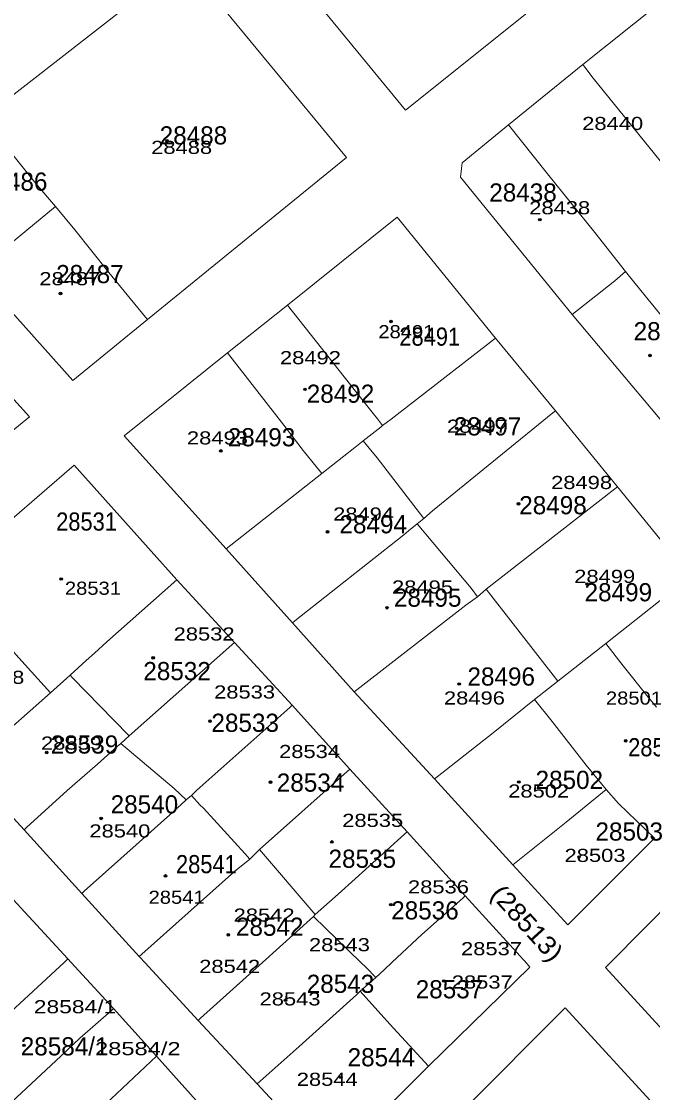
# Model space of a CAD drawing. Extents: x 650553 to 652508, y 239277 to 241647.
# Drawn here: x 651405.4 to 651530.5, y 240724.2 to 240936.5 of the extents above; entities that cross this region are included whole.
import ezdxf

# ---------------------------------------------------------------- set-up
doc = ezdxf.new("R2010")
doc.units = 0
doc.header["$PDMODE"] = 32
doc.header["$PDSIZE"] = 0.5
for name, color, linetype in [('19', 7, 'Continuous'), ('20', 7, 'Continuous'), ('6', 7, 'Continuous')]:
    doc.layers.add(name, color=color, linetype=linetype)
doc.layers.add('3', color=7, linetype='Continuous', lineweight=13)
doc.layers.add('5', color=7, linetype='Continuous', lineweight=13)

msp = doc.modelspace()

# ---------------------------------------------------------------- linework, layer by layer
at = {"layer": '3'}
for p, q in [((651446.19, 240870.77), (651458.08, 240880.24)), ((651522.14, 240750), (651543.89, 240772.06))]:
    msp.add_line(p, q, dxfattribs=at)
for points in [[(651546.27, 240951.81), (651531.67, 240939.91), (651516.66, 240927.91), (651501.92, 240915.97)], [(651437.75, 240948.31), (651469.83, 240909.51), (651430.38, 240877.39)], [(651509.19, 240941.06), (651481.51, 240918.86), (651464.1, 240940.04)], [(651501.92, 240915.97), (651492.74, 240908.47), (651492.4, 240905.62), (651514.54, 240878.38)], [(651430.38, 240877.39), (651415.54, 240865.35), (651396.3, 240886.8), (651380.56, 240904.16)], [(651458.08, 240880.24), (651479.87, 240897.65), (651499.31, 240873.72)], [(651388.92, 240878), (651406.98, 240858.1), (651385.53, 240840.68)], [(651514.54, 240878.38), (651535.4, 240853.59), (651549.69, 240835.74)], [(651499.31, 240873.72), (651511.23, 240859.29), (651523.5, 240844.24), (651538, 240826.47)], [(651445.92, 240831.96), (651425.74, 240854.38), (651446.19, 240870.77)], [(651390.1, 240826.37), (651415.79, 240848.55), (651436.19, 240825.84)], [(651502.8, 240769.36), (651487.27, 240786.38), (651471.34, 240803.62), (651459.09, 240817.33), (651445.92, 240831.96)], [(651436.19, 240825.84), (651447.59, 240813.4), (651459.05, 240800.99), (651470.46, 240788.31), (651481.81, 240775.9), (651493.35, 240763.21), (651505.639, 240749.709)], [(651375, 240810.41), (651394.45, 240788.7), (651405.88, 240776.28), (651417.31, 240763.69), (651428.702, 240751.214)], [(651375, 240793.89), (651381.88, 240786.41), (651393.61, 240773.4), (651414.55, 240750.7), (651415.19, 240750)], [(651530.84, 240774.62), (651513.67, 240757.48), (651502.8, 240769.36)], [(651432.124, 240731.442), (651423.639, 240740.872), (651415.19, 240750)], [(651428.702, 240751.214), (651428.86, 240751.04), (651429.82, 240750)], [(651429.82, 240750), (651440.379, 240738.517), (651452.07, 240725.954)], [(651486.051, 240729.467), (651506.176, 240749.102), (651505.639, 240749.709)], [(651522.14, 240750), (651521.163, 240749.011), (651539.59, 240728.862)], [(651492.971, 240720.815), (651513.155, 240740.984), (651531.466, 240721.038), (651544.042, 240707.095)], [(651450.066, 240711.621), (651441.147, 240721.392), (651432.124, 240731.442)], [(651452.07, 240725.954), (651466.7, 240710.154), (651486.051, 240729.467)]]:
    msp.add_lwpolyline(points, dxfattribs=at)
at = {"layer": '5'}
for p, q in [((651396.3, 240886.8), (651412.1, 240899.78)), ((651525.14, 240886.94), (651528.17, 240883.13)), ((651537.239, 240871.964), (651528.17, 240883.13)), ((651476.97, 240856.39), (651476.65, 240856.11)), ((651464.93, 240846.88), (651471.48, 240852.07)), ((651511.71, 240805.76), (651497.47, 240823.96)), ((651411.14, 240803.44), (651414.99, 240806.932)), ((651426.72, 240794.89), (651423.65, 240798)), ((651414.55, 240750.7), (651413.8, 240750))]:
    msp.add_line(p, q, dxfattribs=at)
for points in [[(651397.68, 240917.22), (651399.98, 240918.99), (651432.63, 240944.47)], [(651516.66, 240927.91), (651517.037, 240927.41), (651518.73, 240925.21)], [(651518.73, 240925.21), (651560.268, 240873.976), (651560.673, 240873.476)], [(651430.38, 240877.39), (651429.968, 240877.89), (651422.71, 240886.7), (651415.97, 240895.15), (651412.1, 240899.78), (651408.2, 240904.34), (651401.46, 240912.71), (651400.99, 240913.24), (651397.68, 240917.22)], [(651501.92, 240915.97), (651509.67, 240906.26), (651519, 240894.67), (651525.14, 240886.94), (651523.01, 240885.07), (651514.54, 240878.38)], [(651458.08, 240880.24), (651475.08, 240858.77), (651475.98, 240857.69), (651476.97, 240856.39), (651478.63, 240857.66), (651499.31, 240873.72)], [(651446.19, 240870.77), (651457.86, 240855.89), (651461.23, 240851.46), (651464.93, 240846.88), (651445.92, 240831.96)], [(651511.23, 240859.29), (651510.73, 240858.884), (651486.86, 240839.48)], [(651473.09, 240853.35), (651475.46, 240855.22), (651476.65, 240856.11)], [(651485.13, 240837.96), (651475.87, 240849.97), (651474.3, 240851.91), (651473.09, 240853.35), (651471.48, 240852.07)], [(651497.47, 240823.96), (651523, 240843.85), (651523.5, 240844.24)], [(651483.82, 240836.95), (651485.13, 240837.96), (651486.86, 240839.48)], [(651495.76, 240822.48), (651494.54, 240824.16), (651485.54, 240834.9), (651484.88, 240835.66), (651483.82, 240836.95), (651482.07, 240835.5), (651481.16, 240834.77)], [(651459.09, 240817.33), (651459.59, 240817.725), (651481.16, 240834.77)], [(651538, 240826.47), (651521.21, 240813.2), (651524.67, 240808.76), (651529.34, 240802.91), (651531.25, 240800.58)], [(651419.83, 240811.26), (651422.29, 240813.51), (651436.19, 240825.84)], [(651497.47, 240823.96), (651495.76, 240822.48), (651493.43, 240820.77)], [(651471.34, 240803.62), (651471.84, 240804.008), (651493.43, 240820.77)], [(651426.72, 240794.89), (651447.09, 240812.957), (651447.59, 240813.4)], [(651507.07, 240802.14), (651511.71, 240805.76), (651521.21, 240813.2)], [(651411.14, 240803.44), (651404.847, 240810.382), (651402.77, 240812.7)], [(651414.99, 240806.932), (651418.188, 240809.832), (651419.83, 240811.26)], [(651423.65, 240798), (651415.475, 240806.432), (651414.99, 240806.932)], [(651411.14, 240803.44), (651394.95, 240789.142), (651394.45, 240788.7)], [(651440.75, 240784.68), (651458.55, 240800.544), (651459.05, 240800.99)], [(651487.27, 240786.38), (651487.77, 240786.772), (651498.9, 240795.49), (651507.07, 240802.14), (651510.57, 240797.75), (651517.32, 240789.13), (651521.26, 240784.29), (651513.33, 240777.83), (651502.8, 240769.36)], [(651438.05, 240782.21), (651435.61, 240784.49), (651425.05, 240793.4), (651426.72, 240794.89)], [(651425.05, 240793.4), (651424.33, 240792.82), (651420.45, 240789.29), (651414.43, 240784.05)], [(651452.56, 240772.42), (651469.96, 240787.866), (651470.46, 240788.31)], [(651414.43, 240784.05), (651406.38, 240776.734), (651405.88, 240776.28)], [(651439.09, 240783.1), (651440.05, 240784.08), (651440.75, 240784.68)], [(651521.26, 240784.29), (651523.72, 240781.48), (651530.84, 240774.62)], [(651450.61, 240770.46), (651449.63, 240771.58), (651441.46, 240780.6), (651440.74, 240781.22), (651439.09, 240783.1), (651438.05, 240782.21), (651435.39, 240779.8)], [(651435.39, 240779.8), (651417.81, 240764.136), (651417.31, 240763.69)], [(651471.51, 240766.59), (651481.31, 240775.448), (651481.81, 240775.9)], [(651447.59, 240768.02), (651450.61, 240770.46), (651452.56, 240772.42)], [(651463.28, 240759.08), (651463.57, 240759.48), (651452.56, 240772.42)], [(651428.702, 240751.214), (651429.22, 240751.675), (651447.59, 240768.02)], [(651463.57, 240759.48), (651468.15, 240763.55), (651471.51, 240766.59)], [(651493.35, 240763.21), (651492.85, 240762.765), (651484.72, 240755.53), (651478.838, 240750.049)], [(651472.62, 240750), (651463.28, 240759.08), (651453.16, 240750)], [(651397.508, 240716.45), (651396.065, 240717.916), (651388.221, 240726.041), (651389.808, 240727.583), (651392.535, 240729.948), (651401.538, 240738.647), (651413.8, 240750)], [(651440.379, 240738.517), (651440.879, 240738.956), (651453.16, 240750)], [(651471.799, 240743.591), (651472.531, 240744.345), (651475.628, 240747.006), (651477.271, 240748.54), (651478.838, 240750.049)], [(651475.628, 240747.006), (651473.674, 240748.977), (651472.62, 240750)], [(651452.07, 240725.954), (651460.412, 240733.359), (651471.799, 240743.591)], [(651486.051, 240729.467), (651478.41, 240737.746), (651472.531, 240744.345)], [(651416.952, 240735.001), (651423.139, 240740.433), (651423.639, 240740.872)], [(651397.508, 240716.45), (651401.448, 240720.514), (651413.187, 240731.421), (651416.952, 240735.001)], [(651406.137, 240706.385), (651417.43, 240717.455), (651422.004, 240721.904), (651432.124, 240731.442)]]:
    msp.add_lwpolyline(points, dxfattribs=at)
at = {"layer": '6'}
for p in [(651434.202, 240912.85), (651508.124, 240897.175), (651413.108, 240882.565), (651478.629, 240877.02), (651529.973, 240870.265), (651461.566, 240863.56), (651491.637, 240855.84), (651444.88, 240851.365), (651503.891, 240840.885), (651466.049, 240835.34), (651413.249, 240825.995), (651517.472, 240825), (651477.817, 240820.285), (651431.484, 240810.365), (651492.145, 240805.17), (651442.742, 240797.805), (651525.15, 240793.91), (651410.368, 240791.606), (651454.735, 240785.725), (651503.958, 240785.75), (651421.177, 240778.545), (651466.907, 240773.895), (651515.897, 240770.885), (651433.91, 240767.157), (651478.583, 240761.453), (651446.369, 240755.468), (651489.097, 240746.338), (651457.721, 240742.517), (651405.871, 240733.575), (651468.679, 240727.249)]:
    msp.add_point(p, dxfattribs=at)

# ---------------------------------------------------------------- texts
at = {"layer": '19'}
for s, p in [('28488', (651432.764, 240912.089)), ('28486', (651397.127, 240902.928)), ('28438', (651498.098, 240900.772)), ('28487', (651412.246, 240884.608)), ('28439', (651526.717, 240873.292)), ('28492', (651461.923, 240860.901)), ('28497', (651491.083, 240854.435)), ('28493', (651446.264, 240852.279)), ('28498', (651504.041, 240838.809)), ('28494', (651468.402, 240835.037)), ('28495', (651479.202, 240820.489)), ('28499', (651517.001, 240821.566)), ('28532', (651429.522, 240805.938)), ('28496', (651493.782, 240804.863)), ('28533', (651443.022, 240795.701)), ('28539', (651411.165, 240791.391)), ('28502', (651507.28, 240784.387)), ('28534', (651455.98, 240783.847)), ('28540', (651423.043, 240779.537)), ('28503', (651519.16, 240774.15)), ('28535', (651466.24, 240768.76)), ('28536', (651478.661, 240758.523)), ('28542', (651447.882, 240755.29)), ('28543', (651461.921, 240743.975)), ('28537', (651483.52, 240742.897)), ('28584/1', (651405.226, 240731.581)), ('28544', (651470.021, 240729.427))]:
    msp.add_text(s, height=3.6, dxfattribs=at).set_placement(p)
at = {"layer": '19', "width": 0.9}
for s, p in [('28491', (651480.282, 240872.216)), ('28531', (651412.244, 240835.574)), ('28501', (651525.639, 240790.853)), ('28541', (651436.002, 240767.683))]:
    msp.add_text(s, height=3.6, dxfattribs=at).set_placement(p)
at = {"layer": '19', "width": 1.1}
msp.add_text('(28513)', height=3.6, rotation=312.283, dxfattribs=at).set_placement((651498.127, 240763.352))
at = {"layer": '20'}
for s, width, p in [('28440', 1.25, (651516.525, 240914.947)), ('28488', 1.25, (651431.083, 240910.21)), ('28438', 1.25, (651506.027, 240898.252)), ('28487', 1.25, (651408.91, 240884.195)), ('28491', 1.15, (651476.113, 240873.691)), ('28492', 1.25, (651456.609, 240868.544)), ('28497', 1.25, (651489.706, 240854.964)), ('28493', 1.25, (651438.17, 240852.645)), ('28498', 1.25, (651510.359, 240843.809)), ('28494', 1.25, (651467.147, 240837.563)), ('28499', 1.25, (651514.947, 240825.208)), ('28531', 1.15, (651413.977, 240822.86)), ('28495', 1.25, (651478.827, 240823.104)), ('28532', 1.25, (651435.528, 240813.791)), ('28538', 1.25, (651393.838, 240805.202)), ('28533', 1.25, (651443.553, 240802.297)), ('28496', 1.25, (651489.116, 240801.109)), ('28501', 1.15, (651521.231, 240801.089)), ('28539', 1.25, (651409.246, 240792.169)), ('28534', 1.25, (651456.434, 240790.509)), ('28502', 1.25, (651501.857, 240782.677)), ('28535', 1.25, (651468.953, 240776.856)), ('28540', 1.25, (651418.832, 240774.77)), ('28503', 1.25, (651513.031, 240769.92)), ('28536', 1.25, (651481.987, 240763.678)), ('28541', 1.15, (651430.566, 240761.625)), ('28542', 1.25, (651447.421, 240758.088)), ('28543', 1.25, (651462.36, 240752.221)), ('28537', 1.25, (651492.503, 240751.435)), ('28542', 1.25, (651440.601, 240747.928)), ('28537', 1.25, (651490.669, 240744.833)), ('28543', 1.25, (651452.568, 240741.482)), ('28584/1', 1.3, (651407.814, 240739.936)), ('28584/2', 1.35, (651419.949, 240731.63)), ('28544', 1.25, (651459.94, 240725.557))]:
    msp.add_text(s, height=2.6, dxfattribs=dict(at, width=width)).set_placement(p)

doc.saveas('drawing.dxf')
